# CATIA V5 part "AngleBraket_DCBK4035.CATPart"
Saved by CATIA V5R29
Part number: AngleBraket_DCBK4035
Source: Unknown
Bounding box of the stored display mesh (mm): x -17.5 to 17.5, y 0 to 40, z 0 to 40
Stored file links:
  C:\가치같이\SmartFactory_BoxErectorConveyor\Boxing(under)\AngleBraket_DCBK4035.CATPart
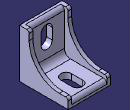
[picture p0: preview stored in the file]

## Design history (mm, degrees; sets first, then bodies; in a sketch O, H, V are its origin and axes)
Body1 (main body)
  Solid1 "PartBody": solid without history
